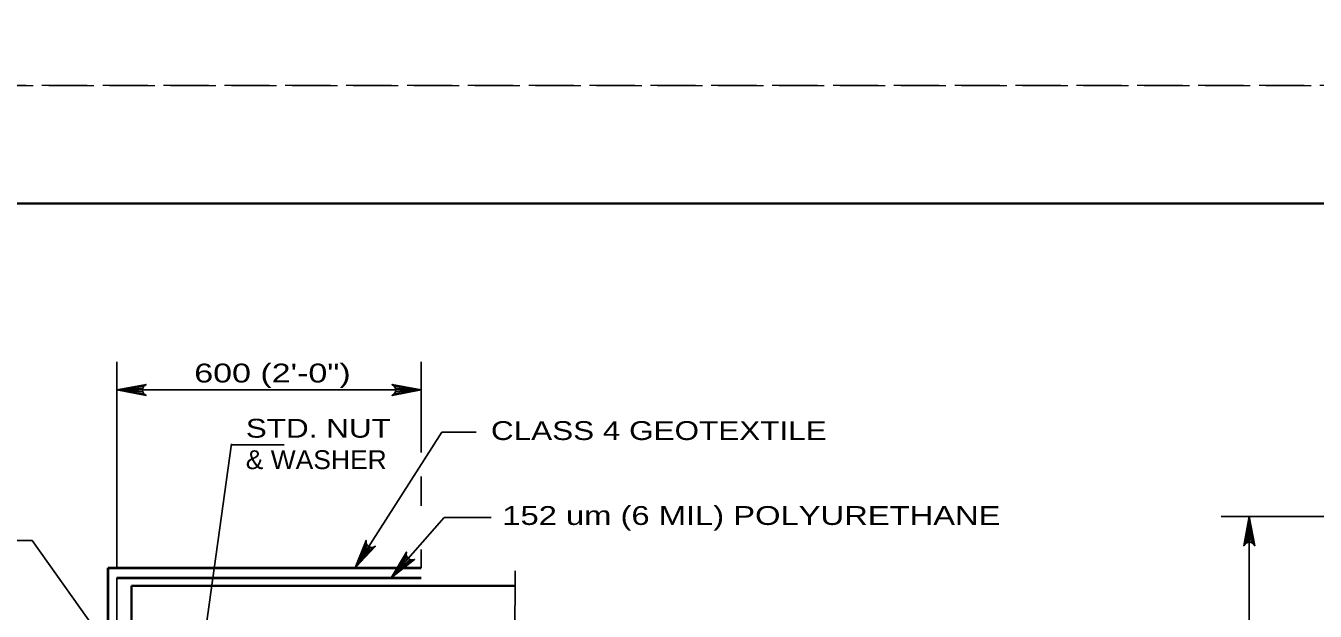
# Model space of a CAD drawing. Extents: x -11 to 79, y -154 to 0.
# Drawn here: x 40.84 to 49.06, y -25.35 to -21.62 of the extents above; entities that cross this region are included whole.
import ezdxf
from ezdxf.enums import TextEntityAlignment as Align

# ---------------------------------------------------------------- set-up
doc = ezdxf.new("R2010")
doc.units = 0
doc.header["$LTSCALE"] = 0.048
doc.linetypes.add('LONG_DASHED', pattern=[7.5, 6, -1.5])
for name, color, linetype, lineweight in [('1', 7, 'Continuous', 25), ('2', 7, 'Continuous', 35), ('3', 7, 'Continuous', 25), ('5', 7, 'Continuous', 25), ('63', 7, 'LONG_DASHED', 13)]:
    doc.layers.add(name, color=color, linetype=linetype, lineweight=lineweight)

msp = doc.modelspace()

# ---------------------------------------------------------------- hatches: boundary and pattern name
at = {"layer": '3'}
for points in [[(41.53825, -23.91867), (41.53825, -23.95867), (41.41825, -23.93867)], [(43.23908, -23.91867), (43.23908, -23.95867), (43.35908, -23.93867)], [(48.61792, -24.86467), (48.65792, -24.86467), (48.63792, -24.74467)], [(42.93642, -25.07242), (43.0095, -24.97675), (42.99267, -24.96592)], [(43.16717, -25.13433), (43.25383, -25.05075), (43.23883, -25.03758)]]:
    msp.add_hatch(color=256, dxfattribs=at).paths.add_polyline_path(points)

# ---------------------------------------------------------------- linework, layer by layer
at = {"layer": '1', "lineweight": 35}
msp.add_lwpolyline([(35.75, -43.25), (67.25, -43.25), (67.25, -22.75), (35.75, -22.75)], close=True, dxfattribs=at)
at = {"layer": '2', "lineweight": 25}
msp.add_lwpolyline([(48.63792, -24.74467), (48.67283, -24.93108), (48.66292, -24.91675), (48.65042, -24.90933), (48.63792, -24.90717), (48.62542, -24.90933), (48.61292, -24.91675), (48.603, -24.93108), (48.63792, -24.74467), (48.61292, -24.91675), (48.62542, -24.90933), (48.63792, -24.74467), (48.63792, -24.90717), (48.65042, -24.90933), (48.63792, -24.74467), (48.66292, -24.91675)], dxfattribs=at)
at = {"layer": '3'}
for p, q in [((41.41825, -25.07183), (41.41825, -23.75867)), ((43.35908, -24.33742), (43.35908, -23.75867)), ((43.35908, -23.93867), (41.41825, -23.93867)), ((42.93642, -25.07242), (43.48908, -24.20833)), ((43.48908, -24.20833), (43.70975, -24.20833)), ((41.94767, -25.72608), (42.14983, -24.28242)), ((42.14908, -24.28758), (42.4855, -24.28758)), ((43.35908, -24.67667), (43.35908, -24.4905)), ((43.16717, -25.13433), (43.50408, -24.75058)), ((43.504, -24.75058), (43.80358, -24.75058)), ((51.0925, -24.74467), (48.45792, -24.74467)), ((48.63792, -27.4305), (48.63792, -24.74467)), ((40.87825, -24.89725), (36.02317, -24.89725)), ((41.4685, -25.72608), (40.87825, -24.89725)), ((43.35908, -25.07183), (43.35908, -24.95525)), ((43.95492, -26.63542), (43.95658, -25.09017))]:
    msp.add_line(p, q, dxfattribs=at)
for points in [[(41.41825, -23.93867), (41.60467, -23.90375), (41.59033, -23.91367), (41.58292, -23.92617), (41.58075, -23.93867), (41.58292, -23.95117), (41.59033, -23.96367), (41.60467, -23.97358), (41.41825, -23.93867), (41.59033, -23.96367), (41.58292, -23.95117), (41.41825, -23.93867), (41.58075, -23.93867), (41.58292, -23.92617), (41.41825, -23.93867), (41.59033, -23.91367)], [(43.35908, -23.93867), (43.17267, -23.97358), (43.187, -23.96367), (43.19442, -23.95117), (43.19658, -23.93867), (43.19442, -23.92617), (43.187, -23.91367), (43.17267, -23.90375), (43.35908, -23.93867), (43.187, -23.91367), (43.19442, -23.92617), (43.35908, -23.93867), (43.19658, -23.93867), (43.19442, -23.95117), (43.35908, -23.93867), (43.187, -23.96367)], [(42.93642, -25.07242), (43.00742, -24.89658), (43.00808, -24.914), (43.01458, -24.927), (43.024, -24.9355), (43.03567, -24.94042), (43.05017, -24.94092), (43.06633, -24.93425), (42.93642, -25.07242), (43.05017, -24.94092), (43.03567, -24.94042), (42.93642, -25.07242), (43.024, -24.9355), (43.01458, -24.927), (42.93642, -25.07242), (43.00808, -24.914)], [(43.16717, -25.13433), (43.26392, -24.97117), (43.26192, -24.98858), (43.26642, -25.00233), (43.27442, -25.01225), (43.28517, -25.01883), (43.2995, -25.0215), (43.31642, -25.01733), (43.16717, -25.13433), (43.2995, -25.0215), (43.28517, -25.01883), (43.16717, -25.13433), (43.27442, -25.01225), (43.26642, -25.00233), (43.16717, -25.13433), (43.26192, -24.98858)]]:
    msp.add_lwpolyline(points, dxfattribs=at)
for points in [[(41.53825, -23.91867), (41.53825, -23.95867), (41.41825, -23.93867)], [(43.23908, -23.91867), (43.23908, -23.95867), (43.35908, -23.93867)], [(48.61792, -24.86467), (48.65792, -24.86467), (48.63792, -24.74467)], [(42.93642, -25.07242), (43.0095, -24.97675), (42.99267, -24.96592)], [(43.16717, -25.13433), (43.25383, -25.05075), (43.23883, -25.03758)]]:
    msp.add_lwpolyline(points, close=True, dxfattribs=at)
at = {"layer": '5', "lineweight": 40}
for p, q in [((41.3625, -25.07242), (43.35908, -25.07242)), ((41.3625, -28.0665), (41.3625, -25.07242)), ((41.41825, -25.13433), (43.35908, -25.13433))]:
    msp.add_line(p, q, dxfattribs=at)
at = {"layer": '5'}
msp.add_line((41.41825, -28.0045), (41.41825, -25.13433), dxfattribs=at)
at = {"layer": '5', "lineweight": 35}
for p, q in [((41.51225, -27.91692), (41.51225, -25.18558)), ((41.51225, -25.18558), (43.95625, -25.18558))]:
    msp.add_line(p, q, dxfattribs=at)
at = {"layer": '63'}
for points in [[(34, -22), (68, -22), (68, 0), (34, 0)], [(34, -44), (68, -44), (68, -22), (34, -22)]]:
    msp.add_lwpolyline(points, close=True, dxfattribs=at)

# ---------------------------------------------------------------- texts
at = {"layer": '3', "width": 1.35}
msp.add_text('600 (2\'-0")', height=0.12, dxfattribs=at).set_placement((42.41013, -23.89075), align=Align.CENTER)
at = {"layer": '3'}
for s, width, p in [('STD. NUT', 1.25, (42.23983, -24.24242)), ('CLASS 4 GEOTEXTILE', 1.25, (43.80308, -24.25733)), ('& WASHER', 1.05, (42.23983, -24.44242))]:
    msp.add_text(s, height=0.12, dxfattribs=dict(at, width=width)).set_placement(p)
at = {"layer": '3', "width": 1.3}
msp.add_text('152 um (6 MIL) POLYURETHANE', height=0.12, dxfattribs=at).set_placement((47.05175, -24.79825), align=Align.RIGHT)

doc.saveas('drawing.dxf')
